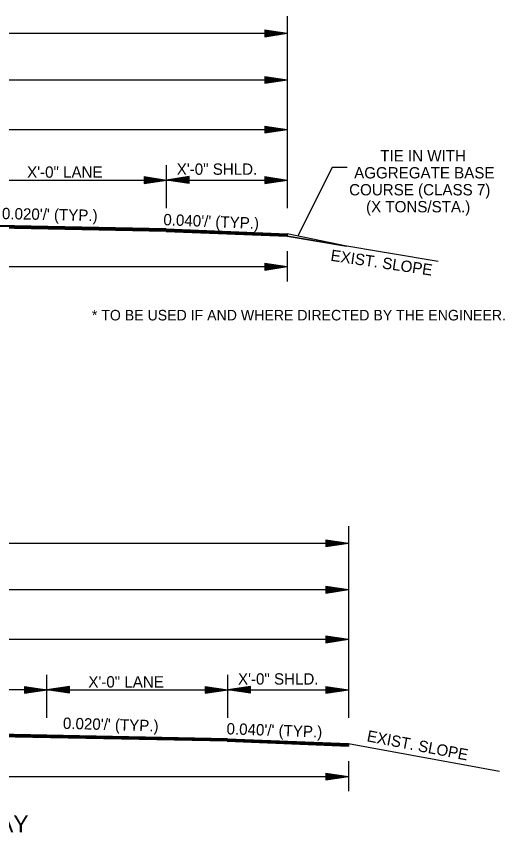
# Model space of a CAD drawing. Extents: x 542112 to 1930787, y -1968972 to 596640.
# Drawn here: x 547046 to 547370, y -1962411 to -1961870 of the extents above; entities that cross this region are included whole.
import ezdxf

# ---------------------------------------------------------------- set-up
doc = ezdxf.new("R2010")
doc.units = 0
doc.layers.add('R_Border Prem', color=7, linetype='Continuous')
doc.layers.add('R_Draft', color=7, linetype='Continuous')

msp = doc.modelspace()

# ---------------------------------------------------------------- linework, layer by layer
at = {"layer": 'R_Draft'}
for p, q in [((547210.74, -1961878.56), (547225.74, -1961880.81)), ((547210.74, -1961878.56), (547210.74, -1961883.06)), ((547210.74, -1961878.94), (547223.24, -1961880.81)), ((547210.74, -1961879.32), (547220.66, -1961880.81)), ((546585.29, -1961880.81), (547225.74, -1961880.81)), ((547210.74, -1961879.7), (547218.16, -1961880.81)), ((547210.74, -1961880.09), (547215.62, -1961880.81)), ((547210.74, -1961880.46), (547213.11, -1961880.81)), ((547210.74, -1961883.06), (547225.74, -1961880.81)), ((547210.74, -1961881.55), (547215.62, -1961880.81)), ((547210.74, -1961882.31), (547220.66, -1961880.81)), ((547210.74, -1961882.69), (547223.24, -1961880.81)), ((547210.74, -1961881.93), (547218.16, -1961880.81)), ((547210.74, -1961881.17), (547213.11, -1961880.81)), ((546585.29, -1961911.68), (547225.74, -1961911.68)), ((547210.74, -1961909.43), (547225.74, -1961911.68)), ((547210.74, -1961909.43), (547210.74, -1961913.93)), ((547210.74, -1961909.81), (547223.24, -1961911.68)), ((547210.74, -1961910.19), (547220.66, -1961911.68)), ((547210.74, -1961910.57), (547218.16, -1961911.68)), ((547210.74, -1961910.96), (547215.62, -1961911.68)), ((547210.74, -1961911.33), (547213.11, -1961911.68)), ((547210.74, -1961913.93), (547225.74, -1961911.68)), ((547210.74, -1961912.42), (547215.62, -1961911.68)), ((547210.74, -1961913.18), (547220.66, -1961911.68)), ((547210.74, -1961913.56), (547223.24, -1961911.68)), ((547210.74, -1961912.8), (547218.16, -1961911.68)), ((547210.74, -1961912.04), (547213.11, -1961911.68)), ((547210.74, -1961942.36), (547225.74, -1961944.61)), ((547210.74, -1961942.36), (547210.74, -1961946.86)), ((547210.74, -1961942.74), (547223.24, -1961944.61)), ((547210.74, -1961943.12), (547220.66, -1961944.61)), ((547210.74, -1961943.49), (547218.16, -1961944.61)), ((547210.74, -1961943.88), (547215.62, -1961944.61)), ((547210.74, -1961944.26), (547213.11, -1961944.61)), ((546585.29, -1961944.61), (547225.74, -1961944.61)), ((547210.74, -1961946.86), (547225.74, -1961944.61)), ((547210.74, -1961945.35), (547215.62, -1961944.61)), ((547210.74, -1961946.1), (547220.66, -1961944.61)), ((547210.74, -1961946.49), (547223.24, -1961944.61)), ((547210.74, -1961945.73), (547218.16, -1961944.61)), ((547210.74, -1961944.96), (547213.11, -1961944.61)), ((547145.74, -1961996.8), (547145.74, -1961968.25)), ((547130.74, -1961975.9), (547145.74, -1961978.15)), ((547130.74, -1961975.9), (547130.74, -1961980.4)), ((547130.74, -1961976.27), (547143.24, -1961978.15)), ((547130.74, -1961976.66), (547140.66, -1961978.15)), ((547130.74, -1961977.03), (547138.16, -1961978.15)), ((547160.74, -1961975.9), (547145.74, -1961978.15)), ((547160.74, -1961976.27), (547148.25, -1961978.15)), ((547160.74, -1961976.66), (547150.83, -1961978.15)), ((547160.74, -1961977.03), (547153.32, -1961978.15)), ((547160.74, -1961980.4), (547160.74, -1961975.9)), ((547210.74, -1961975.9), (547225.74, -1961978.15)), ((547210.74, -1961975.9), (547210.74, -1961980.4)), ((547210.74, -1961976.27), (547223.24, -1961978.15)), ((547210.74, -1961976.66), (547220.66, -1961978.15)), ((547210.74, -1961977.03), (547218.16, -1961978.15)), ((547025.74, -1961978.15), (547145.74, -1961978.15)), ((547130.74, -1961977.42), (547135.62, -1961978.15)), ((547130.74, -1961977.8), (547133.11, -1961978.15)), ((547130.74, -1961980.4), (547145.74, -1961978.15)), ((547130.74, -1961978.88), (547135.62, -1961978.15)), ((547130.74, -1961979.64), (547140.66, -1961978.15)), ((547130.74, -1961980.02), (547143.24, -1961978.15)), ((547130.74, -1961979.27), (547138.16, -1961978.15)), ((547130.74, -1961978.5), (547133.11, -1961978.15)), ((547145.74, -1961978.15), (547225.74, -1961978.15)), ((547160.74, -1961980.4), (547145.74, -1961978.15)), ((547160.74, -1961980.02), (547148.25, -1961978.15)), ((547160.74, -1961979.64), (547150.83, -1961978.15)), ((547160.74, -1961979.27), (547153.32, -1961978.15)), ((547160.74, -1961977.41), (547155.87, -1961978.15)), ((547160.74, -1961978.88), (547155.87, -1961978.15)), ((547160.74, -1961977.8), (547158.37, -1961978.15)), ((547160.74, -1961978.5), (547158.37, -1961978.15)), ((547210.74, -1961977.42), (547215.62, -1961978.15)), ((547210.74, -1961977.8), (547213.11, -1961978.15)), ((547210.74, -1961980.4), (547225.74, -1961978.15)), ((547210.74, -1961978.88), (547215.62, -1961978.15)), ((547210.74, -1961979.64), (547220.66, -1961978.15)), ((547210.74, -1961980.02), (547223.24, -1961978.15)), ((547210.74, -1961979.27), (547218.16, -1961978.15)), ((547210.74, -1961978.5), (547213.11, -1961978.15)), ((547145.38, -1962012.05), (546905.45, -1962007.25)), ((547145.37, -1962012.25), (546905.45, -1962007.45)), ((547145.39, -1962011.45), (546905.46, -1962006.65)), ((547145.38, -1962011.75), (546905.46, -1962006.95)), ((547145.4, -1962011.15), (546905.47, -1962006.35)), ((547145.41, -1962010.55), (546905.48, -1962005.76)), ((547145.4, -1962010.85), (546905.48, -1962006.05)), ((547145.34, -1962012.25), (547225.74, -1962015.47)), ((547145.35, -1962012.05), (547225.74, -1962015.27)), ((547145.36, -1962011.75), (547225.74, -1962014.97)), ((547145.37, -1962011.45), (547225.74, -1962014.67)), ((547145.38, -1962011.15), (547225.74, -1962014.37)), ((547145.4, -1962010.85), (547225.74, -1962014.07)), ((547145.41, -1962010.55), (547225.74, -1962013.77)), ((547225.74, -1962013.77), (547225.74, -1962015.47)), ((547264.99, -1962022), (547225.74, -1962013.77)), ((547225.74, -1962013.77), (547225.74, -1962015.47)), ((547225.74, -1962013.77), (547225.74, -1962015.47)), ((547225.74, -1962013.77), (547225.74, -1962015.47)), ((547325.81, -1962032.14), (547225.74, -1962015.47)), ((547225.74, -1962015.47), (547225.74, -1962015.47)), ((547225.74, -1962015.47), (547264.99, -1962022)), ((547225.74, -1962025.36), (547225.74, -1962045.36)), ((546585.29, -1962035.61), (547225.74, -1962035.61)), ((547210.74, -1962033.36), (547225.74, -1962035.61)), ((547210.74, -1962033.36), (547210.74, -1962037.86)), ((547210.74, -1962033.74), (547223.24, -1962035.61)), ((547210.74, -1962034.12), (547220.66, -1962035.61)), ((547210.74, -1962034.5), (547218.16, -1962035.61)), ((547210.74, -1962034.89), (547215.62, -1962035.61)), ((547210.74, -1962035.26), (547213.11, -1962035.61)), ((547210.74, -1962037.86), (547225.74, -1962035.61)), ((547210.74, -1962036.35), (547215.62, -1962035.61)), ((547210.74, -1962037.11), (547220.66, -1962035.61)), ((547210.74, -1962037.49), (547223.24, -1962035.61)), ((547210.74, -1962036.73), (547218.16, -1962035.61)), ((547210.74, -1962035.97), (547213.11, -1962035.61)), ((546625.91, -1962218.98), (547266.36, -1962218.98)), ((547251.36, -1962216.73), (547266.36, -1962218.98)), ((547251.36, -1962216.73), (547251.36, -1962221.23)), ((547251.36, -1962217.11), (547263.85, -1962218.98)), ((547251.36, -1962217.49), (547261.27, -1962218.98)), ((547251.36, -1962217.87), (547258.78, -1962218.98)), ((547251.36, -1962218.26), (547256.23, -1962218.98)), ((547251.36, -1962218.63), (547253.73, -1962218.98)), ((547251.36, -1962221.23), (547266.36, -1962218.98)), ((547251.36, -1962219.72), (547256.23, -1962218.98)), ((547251.36, -1962220.48), (547261.27, -1962218.98)), ((547251.36, -1962220.86), (547263.85, -1962218.98)), ((547251.36, -1962220.1), (547258.78, -1962218.98)), ((547251.36, -1962219.34), (547253.73, -1962218.98)), ((547251.36, -1962247.6), (547266.36, -1962249.85)), ((547251.36, -1962247.6), (547251.36, -1962252.1)), ((546625.91, -1962249.85), (547266.36, -1962249.85)), ((547251.36, -1962247.98), (547263.85, -1962249.85)), ((547251.36, -1962248.36), (547261.27, -1962249.85)), ((547251.36, -1962248.74), (547258.78, -1962249.85)), ((547251.36, -1962249.13), (547256.23, -1962249.85)), ((547251.36, -1962249.5), (547253.73, -1962249.85)), ((547251.36, -1962252.1), (547266.36, -1962249.85)), ((547251.36, -1962250.59), (547256.23, -1962249.85)), ((547251.36, -1962251.35), (547261.27, -1962249.85)), ((547251.36, -1962251.73), (547263.85, -1962249.85)), ((547251.36, -1962250.97), (547258.78, -1962249.85)), ((547251.36, -1962250.21), (547253.73, -1962249.85)), ((546625.91, -1962282.78), (547266.36, -1962282.78)), ((547251.36, -1962280.53), (547266.36, -1962282.78)), ((547251.36, -1962280.53), (547251.36, -1962285.03)), ((547251.36, -1962280.91), (547263.85, -1962282.78)), ((547251.36, -1962281.29), (547261.27, -1962282.78)), ((547251.36, -1962281.67), (547258.78, -1962282.78)), ((547251.36, -1962282.06), (547256.23, -1962282.78)), ((547251.36, -1962282.43), (547253.73, -1962282.78)), ((547251.36, -1962285.03), (547266.36, -1962282.78)), ((547251.36, -1962283.52), (547256.23, -1962282.78)), ((547251.36, -1962284.28), (547261.27, -1962282.78)), ((547251.36, -1962284.66), (547263.85, -1962282.78)), ((547251.36, -1962283.9), (547258.78, -1962282.78)), ((547251.36, -1962283.14), (547253.73, -1962282.78)), ((547066.36, -1962334.97), (547066.36, -1962306.42)), ((547186.36, -1962334.97), (547186.36, -1962306.42)), ((547066.36, -1962316.32), (546946.1, -1962316.32)), ((547051.36, -1962314.07), (547066.36, -1962316.32)), ((547051.36, -1962314.07), (547051.36, -1962318.57)), ((547051.36, -1962314.44), (547063.85, -1962316.32)), ((547051.36, -1962314.83), (547061.27, -1962316.32)), ((547051.36, -1962315.2), (547058.78, -1962316.32)), ((547051.36, -1962315.59), (547056.23, -1962316.32)), ((547051.36, -1962315.97), (547053.73, -1962316.32)), ((547051.36, -1962318.57), (547066.36, -1962316.32)), ((547051.36, -1962317.05), (547056.23, -1962316.32)), ((547051.36, -1962317.81), (547061.27, -1962316.32)), ((547051.36, -1962318.19), (547063.85, -1962316.32)), ((547051.36, -1962317.44), (547058.78, -1962316.32)), ((547051.36, -1962316.67), (547053.73, -1962316.32)), ((547081.36, -1962314.07), (547066.36, -1962316.32)), ((547066.36, -1962316.32), (547186.36, -1962316.32)), ((547081.36, -1962318.57), (547066.36, -1962316.32)), ((547081.36, -1962314.44), (547068.86, -1962316.32)), ((547081.36, -1962318.19), (547068.86, -1962316.32)), ((547081.36, -1962314.83), (547071.44, -1962316.32)), ((547081.36, -1962317.81), (547071.44, -1962316.32)), ((547081.36, -1962315.2), (547073.94, -1962316.32)), ((547081.36, -1962317.44), (547073.94, -1962316.32)), ((547081.36, -1962315.58), (547076.48, -1962316.32)), ((547081.36, -1962317.05), (547076.48, -1962316.32)), ((547081.36, -1962315.97), (547078.99, -1962316.32)), ((547081.36, -1962316.67), (547078.99, -1962316.32)), ((547081.36, -1962318.57), (547081.36, -1962314.07)), ((547171.36, -1962314.07), (547186.36, -1962316.32)), ((547171.36, -1962314.07), (547171.36, -1962318.57)), ((547171.36, -1962314.44), (547183.85, -1962316.32)), ((547171.36, -1962314.83), (547181.27, -1962316.32)), ((547171.36, -1962315.2), (547178.78, -1962316.32)), ((547171.36, -1962315.59), (547176.23, -1962316.32)), ((547171.36, -1962315.97), (547173.73, -1962316.32)), ((547171.36, -1962318.57), (547186.36, -1962316.32)), ((547171.36, -1962317.05), (547176.23, -1962316.32)), ((547171.36, -1962317.81), (547181.27, -1962316.32)), ((547171.36, -1962318.19), (547183.85, -1962316.32)), ((547171.36, -1962317.44), (547178.78, -1962316.32)), ((547171.36, -1962316.67), (547173.73, -1962316.32)), ((547201.36, -1962314.07), (547186.36, -1962316.32)), ((547186.36, -1962316.32), (547266.36, -1962316.32)), ((547201.36, -1962318.57), (547186.36, -1962316.32)), ((547201.36, -1962314.44), (547188.86, -1962316.32)), ((547201.36, -1962318.19), (547188.86, -1962316.32)), ((547201.36, -1962314.83), (547191.44, -1962316.32)), ((547201.36, -1962317.81), (547191.44, -1962316.32)), ((547201.36, -1962315.2), (547193.94, -1962316.32)), ((547201.36, -1962317.44), (547193.94, -1962316.32)), ((547201.36, -1962315.58), (547196.48, -1962316.32)), ((547201.36, -1962317.05), (547196.48, -1962316.32)), ((547201.36, -1962315.97), (547198.99, -1962316.32)), ((547201.36, -1962316.67), (547198.99, -1962316.32)), ((547201.36, -1962318.57), (547201.36, -1962314.07)), ((547251.36, -1962314.07), (547266.36, -1962316.32)), ((547251.36, -1962314.07), (547251.36, -1962318.57)), ((547251.36, -1962314.44), (547263.85, -1962316.32)), ((547251.36, -1962314.83), (547261.27, -1962316.32)), ((547251.36, -1962315.2), (547258.78, -1962316.32)), ((547251.36, -1962315.59), (547256.23, -1962316.32)), ((547251.36, -1962315.97), (547253.73, -1962316.32)), ((547251.36, -1962318.57), (547266.36, -1962316.32)), ((547251.36, -1962317.05), (547256.23, -1962316.32)), ((547251.36, -1962317.81), (547261.27, -1962316.32)), ((547251.36, -1962318.19), (547263.85, -1962316.32)), ((547251.36, -1962317.44), (547258.78, -1962316.32)), ((547251.36, -1962316.67), (547253.73, -1962316.32)), ((547186, -1962349.92), (546946.07, -1962345.13)), ((547186.01, -1962349.62), (546946.08, -1962344.83)), ((547186.02, -1962349.02), (546946.09, -1962344.23)), ((547186.01, -1962349.32), (546946.09, -1962344.53)), ((547186.03, -1962348.72), (546946.1, -1962343.93)), ((547185.99, -1962350.42), (546946.06, -1962345.63)), ((547186, -1962350.22), (546946.07, -1962345.43)), ((547185.96, -1962350.42), (547266.36, -1962353.64)), ((547185.97, -1962350.22), (547266.36, -1962353.44)), ((547185.98, -1962349.92), (547266.36, -1962353.14)), ((547185.99, -1962349.62), (547266.36, -1962352.84)), ((547186, -1962349.32), (547266.36, -1962352.54)), ((547186.01, -1962349.02), (547266.36, -1962352.24)), ((547186.03, -1962348.72), (547266.36, -1962351.94)), ((547266.36, -1962351.94), (547266.36, -1962353.64)), ((547266.36, -1962351.94), (547266.36, -1962353.64)), ((547266.36, -1962351.94), (547366.43, -1962370.32)), ((547266.36, -1962363.54), (547266.36, -1962383.54)), ((547251.36, -1962371.53), (547266.36, -1962373.78)), ((547251.36, -1962371.53), (547251.36, -1962376.03)), ((547251.36, -1962371.91), (547263.85, -1962373.78)), ((547251.36, -1962372.29), (547261.27, -1962373.78)), ((546625.91, -1962373.78), (547266.36, -1962373.78)), ((547251.36, -1962372.67), (547258.78, -1962373.78)), ((547251.36, -1962373.06), (547256.23, -1962373.78)), ((547251.36, -1962373.43), (547253.73, -1962373.78)), ((547251.36, -1962376.03), (547266.36, -1962373.78)), ((547251.36, -1962374.52), (547256.23, -1962373.78)), ((547251.36, -1962375.28), (547261.27, -1962373.78)), ((547251.36, -1962375.66), (547263.85, -1962373.78)), ((547251.36, -1962374.9), (547258.78, -1962373.78)), ((547251.36, -1962374.14), (547253.73, -1962373.78))]:
    msp.add_line(p, q, dxfattribs=at)
for points in [[(547225.74, -1961869.55), (547225.74, -1961996.8)], [(547265.43, -1961969.93), (547255.43, -1961969.93), (547232.65, -1962015.22)], [(547266.36, -1962207.72), (547266.36, -1962334.97)]]:
    msp.add_lwpolyline(points, dxfattribs=at)

# ---------------------------------------------------------------- texts
at = {"layer": 'R_Border Prem'}
msp.add_text('* TO BE USED IF AND WHERE DIRECTED BY THE ENGINEER.', height=7, dxfattribs=at).set_placement((547096.13, -1962071.28))
at = {"layer": 'R_Draft'}
for s, height, p in [('TIE IN WITH ', 7.5, (547287.37, -1961965.83)), ('X\'-0" LANE', 7.5, (547053.19, -1961976.61)), ('X\'-0" SHLD.', 7.5, (547152.43, -1961974.66)), ('AGGREGATE BASE', 7.5, (547270.07, -1961977.08)), ('COURSE (CLASS 7)', 7.5, (547266.76, -1961988.33)), ('(X TONS/STA.)', 7.5, (547277.98, -1961999.58)), ('X\'-0" LANE', 7.5, (547093.81, -1962314.78)), ('X\'-0" SHLD.', 7.5, (547193.05, -1962312.83)), ('4 LANE OPEN SHOULDER INLAY', 11.25, (546820, -1962410.9))]:
    msp.add_text(s, height=height, dxfattribs=at).set_placement(p)
for s, rotation, p in [("0.020'/' (TYP.)", 358.7889, (547036.44, -1962004.05)), ("0.040'/' (TYP.)", 357.7013, (547143.42, -1962008.05)), ('EXIST. SLOPE', 351.5755, (547254.11, -1962031.65)), ("0.020'/' (TYP.)", 358.3625, (547076.85, -1962342.15)), ("0.040'/' (TYP.)", 358.0466, (547185.36, -1962345.78)), ('EXIST. SLOPE', 349.1171, (547278.09, -1962350.38))]:
    msp.add_text(s, height=7.5, rotation=rotation, dxfattribs=at).set_placement(p)

doc.saveas('drawing.dxf')
